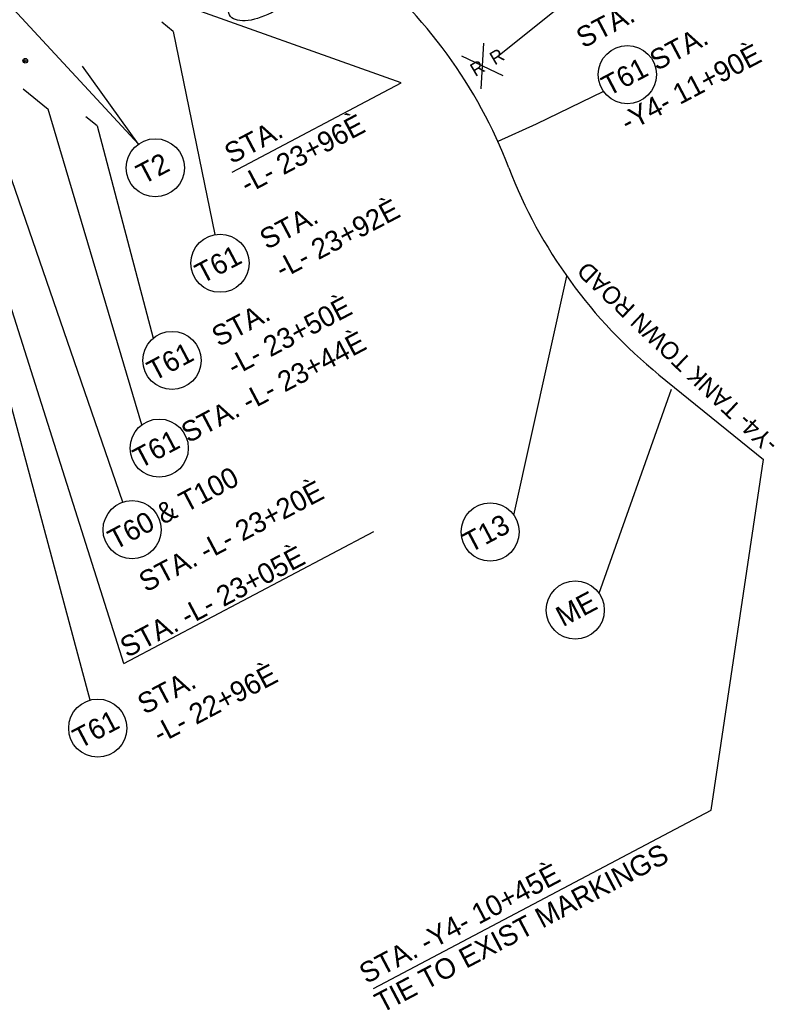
# Model space of a CAD drawing. Extents: x 1487421 to 1489048, y 497792 to 499463.
# Drawn here: x 1488787 to 1489047.9, y 498855 to 499195.5 of the extents above; entities that cross this region are included whole.
import ezdxf

# ---------------------------------------------------------------- set-up
doc = ezdxf.new("R2010")
doc.units = 0
for name, color, linetype in [('DEV TUBULAR MARKER PLAN VIEW CELL', 7, 'Continuous'), ('Prop Horizontal Alignment Direction Label', 7, 'Continuous'), ('Prop Mkg Solid Dbl Yel Rpm 80ft', 7, 'Continuous'), ('Prop Mkg Solid White Stop Bar', 7, 'Continuous'), ('Scratch_Level_3', 7, 'Continuous'), ('Text', 7, 'Continuous')]:
    doc.layers.add(name, color=color, linetype=linetype)

msp = doc.modelspace()

# ---------------------------------------------------------------- linework, layer by layer
at = {"layer": 'DEV TUBULAR MARKER PLAN VIEW CELL'}
for radius in [0.781, 0.332]:
    msp.add_circle((1488788.88, 499181.39), radius, dxfattribs=at)
at = {"layer": 'Prop Mkg Solid Dbl Yel Rpm 80ft'}
msp.add_line((1489006.88, 499073.44), (1489042.83, 499044.3), dxfattribs=at)
for centre, start, end in [((1488796.55, 499083.6), 21.0099, 51.1156), ((1489113.94, 499205.5), 201.0099, 230.9669)]:
    msp.add_arc(centre, 170, start, end, dxfattribs=at)
at = {"layer": 'Prop Mkg Solid White Stop Bar'}
for p, q in [((1488839.72, 499191.46), (1488835.83, 499194.6)), ((1488788.14, 499171.71), (1488796.72, 499164.8)), ((1488813.56, 499159.02), (1488809.66, 499162.16))]:
    msp.add_line(p, q, dxfattribs=at)
at = {"layer": 'Scratch_Level_3'}
for p, q in [((1488972.58, 499199.73), (1488950.83, 499182.38)), ((1488946.48, 499187.47), (1488945.55, 499171.76)), ((1488938.99, 499183.06), (1488953.2, 499176.27)), ((1488987.82, 499170.87), (1488964.67, 499159.59)), ((1488964.67, 499159.59), (1488951.46, 499153.62))]:
    msp.add_line(p, q, dxfattribs=at)
msp.add_circle((1488995.99, 499176.63), 10, dxfattribs=at)
at = {"layer": 'Text'}
for p, q in [((1488918.19, 499173.82), (1488829.46, 499205.43)), ((1488827.84, 499152.76), (1488783.29, 499200.75)), ((1488839.72, 499191.46), (1488854.13, 499121.62)), ((1488827.84, 499152.76), (1488808.61, 499179.57)), ((1488860.07, 499143.12), (1488918.19, 499173.82)), ((1488828.95, 499056.21), (1488796.72, 499164.8)), ((1488813.56, 499159.02), (1488832.87, 499085.96)), ((1488822.39, 499029.61), (1488781.98, 499147.09)), ((1488822.74, 498974.13), (1488772.04, 499134.22)), ((1488811.22, 498961.61), (1488766.64, 499127.39)), ((1488956.99, 499025.17), (1488975.15, 499107.34)), ((1488986.25, 498998.31), (1489011.22, 499068.45)), ((1489024.86, 498923.76), (1489042.83, 499044.3)), ((1488822.74, 498974.13), (1488908.76, 499019.55)), ((1488908.68, 498862.41), (1489024.86, 498923.76))]:
    msp.add_line(p, q, dxfattribs=at)
for centre in [(1488833.6, 499144.58), (1488855.88, 499111.78), (1488839.36, 499078.36), (1488834.95, 499048.21), (1488825.64, 499020.16), (1488948.81, 499019.41), (1488978.07, 498992.55), (1488813.82, 498951.95)]:
    msp.add_circle(centre, 10, dxfattribs=at)
msp.add_ellipse((1488870.71, 499203.25), major_axis=(11.57, 6.11), ratio=0.462467, dxfattribs=at)

# ---------------------------------------------------------------- texts
at = {"layer": 'Prop Horizontal Alignment Direction Label'}
msp.add_text('-Y4- TANK TOWN ROAD', height=6, rotation=136.5026, dxfattribs=at).set_placement((1489048.23, 499050.22))
at = {"layer": 'Scratch_Level_3'}
for s, height, rotation, p in [('STA. -Y4- 12+15È', 7, 27.835, (1488980.84, 499185.53)), ('T61 STA. ', 7, 27.835, (1488989.54, 499169.05)), ('-Y4- 11+90È', 7, 27.835, (1488996.08, 499156.67)), ('R  R', 4.556, 30.5479, (1488943.67, 499175.78))]:
    msp.add_text(s, height=height, rotation=rotation, dxfattribs=at).set_placement(p)
at = {"layer": 'Text'}
for s, p in [('-L- 23+96È', (1488865.25, 499135.43)), ('STA.', (1488859.8, 499145.75)), ('T2', (1488829.51, 499138.73)), ('-L- 23+92È', (1488877.27, 499106.25)), ('STA.', (1488871.96, 499116.31)), ('T61', (1488849.72, 499104.57)), ('-L- 23+50È', (1488860.75, 499072.83)), ('STA.', (1488855.44, 499082.89)), ('T61 STA. -L- 23+44È', (1488828.4, 499041.07)), ('T61', (1488833.2, 499071.14)), ('T60 & T100', (1488819.75, 499013.09)), ('STA. -L- 23+20È', (1488830.4, 498998.51)), ('T13', (1488941.97, 499012.11)), ('STA. -L- 23+05È', (1488823.91, 498976.04)), ('ME', (1488973.84, 498986.62)), ('-L- 22+96È', (1488835.21, 498946.43)), ('STA.', (1488829.9, 498956.49)), ('T61', (1488807.66, 498944.74)), ('TIE TO EXIST MARKINGS', (1488911.52, 498853.85)), ('STA. -Y4- 10+45È', (1488906.2, 498863.91))]:
    msp.add_text(s, height=7, rotation=27.835, dxfattribs=at).set_placement(p)

doc.saveas('drawing.dxf')
